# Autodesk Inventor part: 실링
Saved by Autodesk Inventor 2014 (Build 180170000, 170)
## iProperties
Created: 2026-04
Part Number: 실링
Material: 일반
Document SubType Name: Modeling
Designer: dg
Density: 1 g/cm^3
Appearance: 기본값
Author: dg
Author: jhkim
Creation Date: 2026-03-26
Sending System: Autodesk Inventor 2026
Preprocessor: ST-DEVELOPER v20.1
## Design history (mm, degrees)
node "실링1"
node "솔리드1"
node "기준1"
